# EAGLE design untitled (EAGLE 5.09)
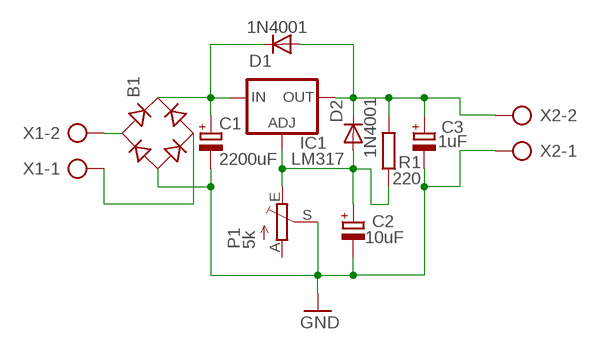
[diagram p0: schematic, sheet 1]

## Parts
B1  RECTIFIER-RB1A  [RB1A]
C1  2200uF  C-POLC7,5_16,18  [C7,5-16,18]
C2  10uF  CPOL-EUE2.5-6  [E2,5-6]
C3  1uF  CPOL-EUE2.5-7  [E2,5-7]
D1  1N4001  DIODE-DO34-7  [DO34-7]
D2  1N4001  DIODE-DO34-7  [DO34-7]
IC1  LM317  LM317TS  [317TS]
P1  5k  TRIM_EU-RJ9W  [RJ9W]
R1  220  R-EU_0207/10  [0207/10]
X1  AK500/2  [AK500/2]
X2  AK500/2  [AK500/2]

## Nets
N$1: C2.+ D2.A IC1.1(ADJ) P1.E R1.1
N$2: B1.AC1 X1.2
N$3: B1.+ C1.+ D1.C IC1.3(IN)
N$4: C3.+ D1.A D2.C IC1.2(OUT) R1.2 X2.2
N$5: B1.AC2 X1.1
S: B1.- C1.- C2.- C3.- P1.S X2.1 ; supply symbol labelled GND
Unconnected: P1.A

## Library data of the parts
B1 = rectifier:RECTIFIER-: Rectifier
C1 = moja:C-POL
C2 C3 = resistor:CPOL-EU: POLARIZED CAPACITOR, European symbol
D1 D2 = diode:DIODE-: DIODE
IC1 = v-reg:LM317TS: VOLTAGE REGULATOR
P1 = pot:TRIM_EU-: POTENTIOMETER
R1 = resistor:R-EU_: RESISTOR, European symbol
X1 X2 = con-ptr500:AK500/2: CONNECTOR

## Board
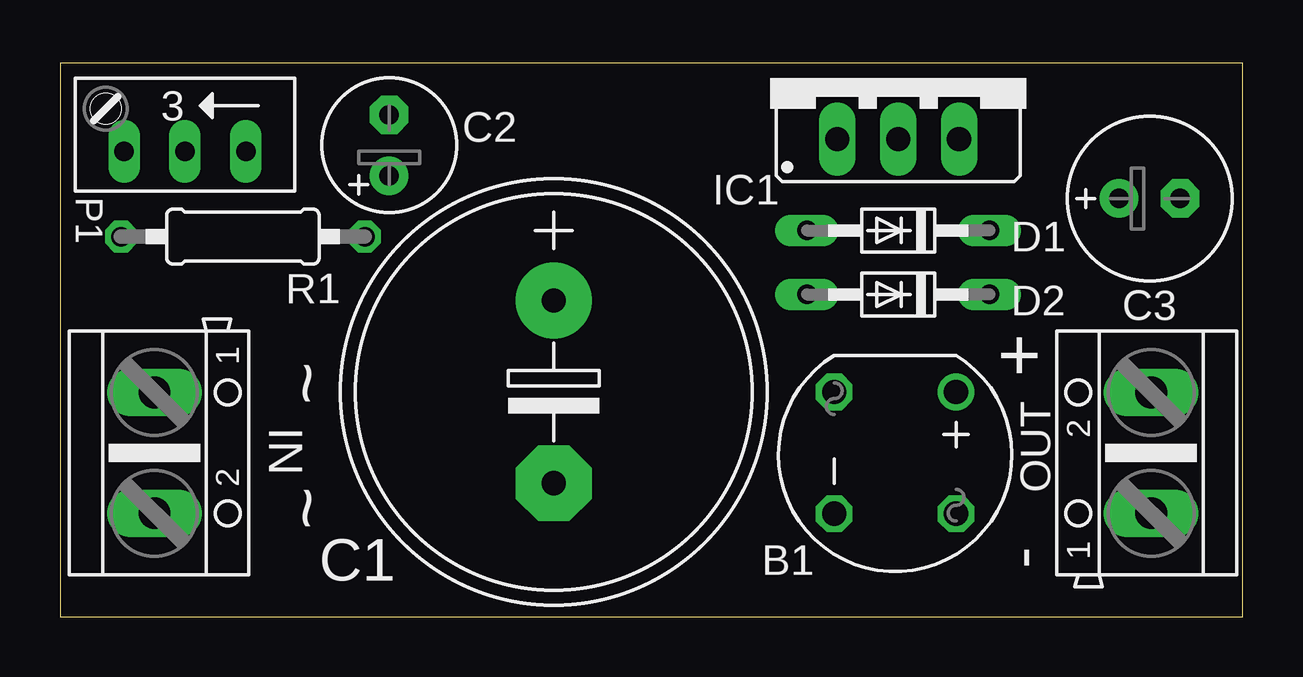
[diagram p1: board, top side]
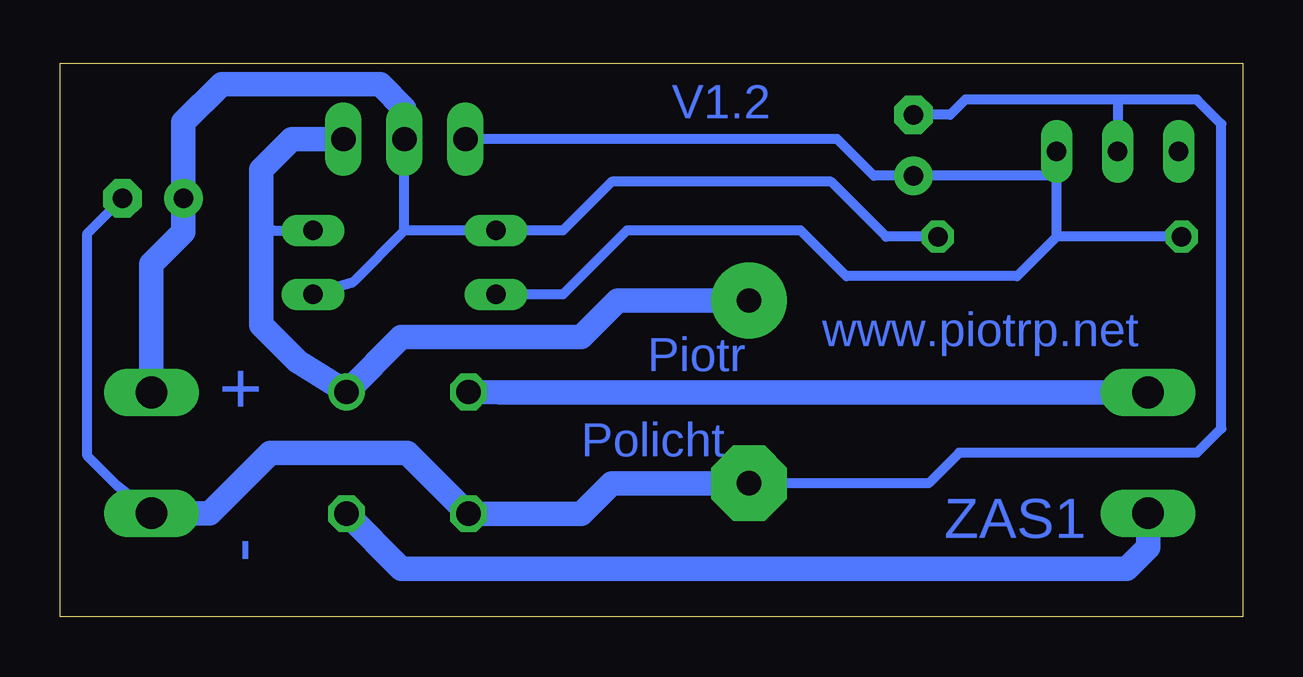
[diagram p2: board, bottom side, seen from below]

Size 49.28 x 23.09 mm. Coordinates in mm from the lower left corner, seen from the top.
Outline: 0,23.09 0,0 49.28,0 49.28,23.09 0,23.09
Copper layers (1*16): Top 0.035mm / dielectric 1.5mm / Bottom 0.035mm
Design rules "default": minimum track width 10mil, minimum drill 24mil, track to track 8mil, track to pad 8mil, pad to pad 8mil, via to via 8mil, smd to smd 8mil, copper to edge 40mil, drill to drill 8mil, minimum pad ring 10mil, minimum via ring 8mil, stop-mask expansion 4mil, vias tented up to drill 0mil, thermal gap 10mil
Milling: 4 lines

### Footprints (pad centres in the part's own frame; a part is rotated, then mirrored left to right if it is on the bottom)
RB1A = drill 1.016 round: + -2.54,2.54 | drill 1.016 octagon: - 2.54,-2.54; AC1 2.54,2.54; AC2 -2.54,-2.54
C7,5-16,18 = drill 1.016 pad 3.15 round: + -3.81,0 | drill 1.016 pad 3.15 octagon: - 3.81,0
E2,5-6 = drill 0.813 pad 1.6 round: + -1.27,0 | drill 0.813 pad 1.6 octagon: - 1.27,0
E2,5-7 = drill 0.813 pad 1.6 round: + -1.27,0 | drill 0.813 pad 1.6 octagon: - 1.27,0
DO34-7 = drill 0.813 long: A 3.81,0; C -3.81,0
317TS = drill 1.016 long: 1 -2.54,-2.54; 2 0,-2.54; 3 2.54,-2.54
RJ9W = drill 0.813 long: A 2.54,0.635; E -2.54,0.635; S 0,0.635
0207/10 = drill 0.813 octagon: 1 -5.08,0; 2 5.08,0
AK500/2 = drill 1.321 long: 1 -2.515,0; 2 2.515,0

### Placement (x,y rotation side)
B1  34.8,6.84 270 top
C1  20.57,9.38 270 top
C2  13.72,19.67 90 top
C3  45.4,17.44 0 top
D1  34.92,16.11 180 top
D2  34.92,13.44 180 top
IC1  34.92,22.46 0 top
P1  5.21,20.05 180 top
R1  7.62,15.85 0 top
X1  3.94,6.84 270 top
X2  45.47,6.84 90 top

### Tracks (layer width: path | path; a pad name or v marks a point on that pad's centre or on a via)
N$1
  Bottom 0.406: 7.75,15.85 7.75,18.39 | 7.75,18.39 P1.E | R1.1 7.75,15.85 | 7.75,15.85 9.4,14.2 16.51,14.2 18.41,16.11 25.65,16.11 28.32,13.44 D2.A | IC1.1 16.89,19.92 15.37,18.39 C2.+ 7.75,18.39
N$2
  Bottom 1.016: X1.2 3.94,2.9 4.83,2.01 35.05,2.01 B1.AC1
N$3
  Bottom 0.406: D1.C 40.39,16.11 40.89,16.24
  Bottom 1.016: IC1.3 39.62,19.92 40.89,18.65 40.89,16.24 40.89,12.17 39.37,10.65 B1.+ 35.05,11.66 27.56,11.66 26.04,13.19 C1.+
N$4
  Bottom 0.406: R1.2 14.86,15.85 17.14,18.14 26.29,18.14 28.32,16.11 D1.A 34.92,16.11 | 34.92,16.11 IC1.2 | 34.92,16.11 37.08,13.95 D2.C
  Bottom 1.016: IC1.2 34.92,21.19 35.94,22.21 42.55,22.21 44.13,20.62 C3.+ 44.13,16.05 45.47,14.71 X2.2
N$5
  Bottom 1.016: X1.1 30.96,9.35 B1.AC2
S
  Bottom 0.406: X2.1 46.89,5.47 48.13,6.71 48.13,15.98 C3.- | C2.- 12.19,20.94 11.56,21.57 5.21,21.57 | 5.21,21.57 1.91,21.57 0.89,20.55 0.89,7.85 1.91,6.84 11.81,6.84 13.08,5.57 C1.- | 5.21,21.57 P1.S
  Bottom 1.016: X2.1 43.03,4.32 40.51,6.84 34.8,6.84 B1.- 27.56,4.3 26.29,5.57 C1.-

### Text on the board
Bottom: V1.2 | Piotr | www.piotrp.net | + | Policht | ZAS1 | -
tNames: ~ | + | IN | ~ | OUT | -
bNames: + | OUT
